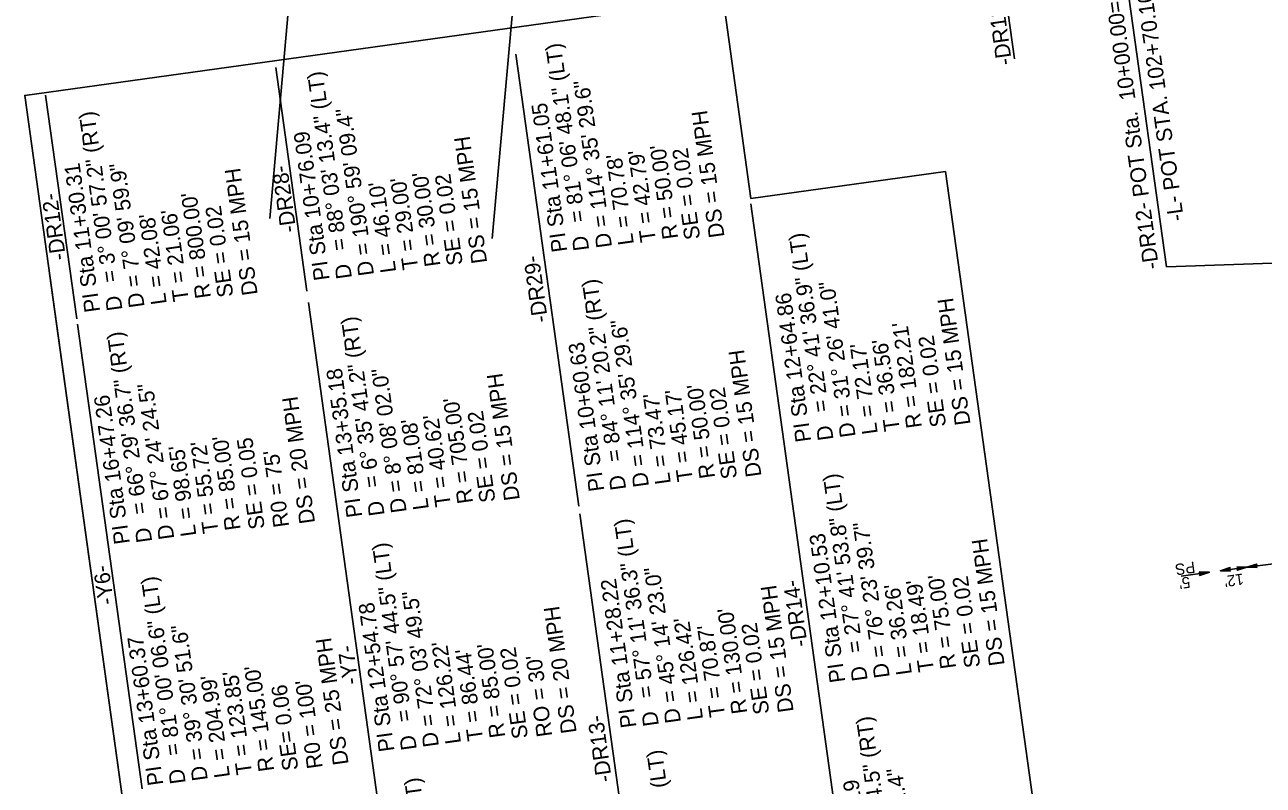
# Model space of a CAD drawing. Extents: x 472216 to 481979, y 489069 to 507339.
# Drawn here: x 477522 to 478077, y 496648 to 496989 of the extents above; entities that cross this region are included whole.
import ezdxf

# ---------------------------------------------------------------- set-up
doc = ezdxf.new("R2010")
doc.units = 0
for name, color, linetype in [('Exist Horizontal Alignment Point', 7, 'Continuous'), ('Old_Level_12', 7, 'Continuous'), ('Prop Rem of Exist Asph Pvmt', 7, 'Continuous'), ('Sheet Plot Border Outside CELL', 7, 'Continuous'), ('Sheet Sticker Incomplete CELL', 7, 'Continuous')]:
    doc.layers.add(name, color=color, linetype=linetype)

msp = doc.modelspace()

# ---------------------------------------------------------------- linework, layer by layer
at = {"layer": 'Exist Horizontal Alignment Point'}
msp.add_lwpolyline([(477581, 496533.88), (477522.1, 496957.12), (477834.84, 497000.65), (477847.32, 496910.94), (477934.43, 496923.06), (477980.85, 496589.53)], close=True, dxfattribs=at)
msp.add_lwpolyline([(477677.06, 496547.25), (477581, 496533.88), (477533.19, 496877.44)], dxfattribs=at)
at = {"layer": 'Old_Level_12'}
for p, q in [((477948.85, 497092.05), (477965.34, 496973.57)), ((478033.45, 496880.38), (478014.2, 497018.75)), ((478165.07, 496885.12), (478033.45, 496880.38))]:
    msp.add_line(p, q, dxfattribs=at)
at = {"layer": 'Prop Rem of Exist Asph Pvmt'}
for p, q in [((477770.17, 496773.32), (477742.01, 496975.64)), ((477648.47, 496869.48), (477634.53, 496969.68)), ((477545.37, 496857.08), (477531.42, 496957.28)), ((477892.86, 496581.03), (477847.28, 496908.56)), ((477692.61, 496552.35), (477649.18, 496864.39)), ((477574.64, 496646.77), (477545.7, 496854.7)), ((477798.8, 496567.57), (477770.65, 496769.88))]:
    msp.add_line(p, q, dxfattribs=at)
at = {"layer": 'Sheet Plot Border Outside CELL'}
for p, q in [((477675.74, 497395.08), (477631.85, 496902.03)), ((477775.34, 497386.21), (477731.46, 496893.16))]:
    msp.add_line(p, q, dxfattribs=at)
at = {"layer": 'Sheet Sticker Incomplete CELL'}
for p, q in [((478081.37, 496747.41), (478069.45, 496746.04)), ((478052.61, 496743.67), (478039.92, 496741.88)), ((478069.44, 496746.04), (478057.56, 496744.37))]:
    msp.add_line(p, q, dxfattribs=at)
for points in [[(478074, 496745.78), (478069.45, 496746.04), (478073.85, 496747.35), (478073.37, 496746.49)], [(478048.05, 496743.81), (478052.61, 496743.67), (478048.24, 496742.25), (478048.7, 496743.12)], [(478062.13, 496744.22), (478057.56, 496744.37), (478061.93, 496745.79), (478061.47, 496744.92)], [(478064.88, 496746.18), (478069.44, 496746.04), (478065.08, 496744.61), (478065.53, 496745.49)]]:
    msp.add_lwpolyline(points, close=True, dxfattribs=at)

# ---------------------------------------------------------------- texts
at = {"layer": 'Old_Level_12'}
for s, p in [('-DR13- PC Sta.  10+57.35', (477964.3, 496971.14)), ('-L- POT STA. 102+70.10', (478041.24, 496901.31)), ('-DR12- POT Sta.  10+00.00=', (478030.1, 496879.78))]:
    msp.add_text(s, height=7, rotation=97.9227, dxfattribs=at).set_placement(p)
at = {"layer": 'Prop Rem of Exist Asph Pvmt'}
for s, rotation, p in [('= 81%%d 06\' 48.1" (LT)', 97.9227, (477773.25, 496900.79)), ('= 88%%d 03\' 13.4" (LT)', 97.9227, (477666.59, 496888.16)), ('D = 114%%d 35\' 29.6"', 97.9227, (477785.12, 496889.38)), ('PI Sta 11+61.05', 97.9227, (477765.14, 496887.45)), ('= 3%%d 00\' 57.2" (RT)', 97.9227, (477563.82, 496873.9)), ('D = 190%%d 59\' 09.4"', 97.9227, (477678.55, 496876.85)), ('DS = 15 MPH', 97.9227, (477835.52, 496893.91)), ('PI Sta 10+76.09', 97.9227, (477658.65, 496874.76)), ('DS = 15 MPH', 97.9227, (477729.2, 496882.35)), ("L = 70.78'", 97.9227, (477794.9, 496890.65)), ("T = 42.79'", 97.9227, (477804.83, 496891.95)), ("R = 50.00'", 97.9227, (477814.76, 496893.24)), ('SE = 0.02', 97.9227, (477824.62, 496893.07)), ('PI Sta 11+30.31', 97.9227, (477555.89, 496860.51)), ('D = 7%%d 09\' 59.9"', 97.9227, (477575.79, 496862.6)), ('DS = 15 MPH', 97.9227, (477626.44, 496868.1)), ('-DR28-', 97.9227, (477643.75, 496896.21)), ("T = 29.00'", 97.9227, (477698.36, 496879.61)), ("R = 30.00'", 97.9227, (477708.27, 496880.99)), ('SE = 0.02', 97.9227, (477718.31, 496881.51)), ("L = 46.10'", 97.9227, (477688.46, 496878.23)), ('-DR12-', 97.9227, (477540.64, 496883.81)), ("R = 800.00'", 97.9227, (477605.51, 496866.73)), ('SE = 0.02', 97.9227, (477615.54, 496867.25)), ("L = 42.08'", 97.9227, (477585.7, 496863.97)), ("T = 21.06'", 97.9227, (477595.6, 496865.35)), ('D', 97.4336, (477774.87, 496888.01)), ('= 22%%d 41\' 36.9" (LT)', 97.9227, (477882.27, 496815.83)), ('D', 97.9227, (477668.65, 496875.47)), ('-DR29-', 97.9227, (477756.46, 496855.92)), ('= 84%%d 11\' 20.2" (RT)', 97.9227, (477789.82, 496793.66)), ('D = 31%%d 26\' 41.0"', 97.9227, (477894.23, 496804.52)), ('D', 97.9227, (477565.89, 496861.22)), ('PI Sta 12+64.86', 97.9227, (477874.33, 496802.43)), ('DS = 15 MPH', 97.9227, (477945.68, 496809.98)), ('= 6%%d 35\' 41.2" (RT)', 97.9227, (477681.21, 496782.05)), ('D = 114%%d 35\' 29.6"', 97.9227, (477801.67, 496782.25)), ("R = 182.21'", 97.9227, (477923.95, 496808.66)), ('= 66%%d 29\' 36.7" (RT)', 97.9227, (477577.12, 496770.11)), ("T = 36.56'", 97.9227, (477914.04, 496807.28)), ('SE = 0.02', 97.9227, (477934.78, 496809.13)), ('PI Sta 10+60.63', 97.9227, (477781.72, 496780.33)), ('DS = 15 MPH', 97.9227, (477852.07, 496786.79)), ("L = 72.17'", 97.9227, (477904.14, 496805.9)), ('PI Sta 13+35.18', 97.9227, (477673.28, 496768.66)), ('D = 8%%d 08\' 02.0"', 97.9227, (477693.18, 496770.74)), ('DS = 15 MPH', 97.9227, (477743.83, 496776.25)), ('D = 67%%d 24\' 24.5"', 97.9227, (477589.09, 496758.8)), ("T = 45.17'", 97.9227, (477821.37, 496784.82)), ("R = 50.00'", 97.9227, (477831.31, 496786.12)), ('SE = 0.02', 97.9227, (477841.17, 496785.94)), ('PI Sta 16+47.26', 97.9227, (477569.18, 496756.71)), ('DS = 20 MPH', 97.9227, (477652.13, 496765.87)), ("R = 705.00'", 97.9227, (477722.89, 496774.88)), ("L = 73.47'", 97.9227, (477811.46, 496783.53)), ("T = 40.62'", 97.9227, (477712.99, 496773.5)), ('SE = 0.02', 97.9227, (477732.93, 496775.4)), ("L = 81.08'", 97.9227, (477703.08, 496772.12)), ('D', 97.9227, (477884.33, 496803.15)), ("R = 85.00'", 97.9227, (477618.8, 496762.94)), ('SE = 0.05', 97.9227, (477629.63, 496763.41)), ("L = 98.65'", 97.9227, (477598.99, 496760.18)), ("T = 55.72'", 97.9227, (477608.9, 496761.56)), ("R0 = 75'", 97.9227, (477640.53, 496764.26)), ('D', 97.9227, (477791.45, 496780.92)), ('= 27%%d 41\' 53.8" (LT)', 97.9227, (477897.56, 496708.11)), ('D', 97.9227, (477683.27, 496769.37)), ('= 57%%d 11\' 36.3" (LT)', 97.9227, (477804.02, 496687.9)), ('D = 76%%d 23\' 39.7"', 97.9227, (477909.52, 496696.8)), ('D', 97.9227, (477579.18, 496757.43)), ('PI Sta 12+10.53', 97.9227, (477889.62, 496694.72)), ('DS = 15 MPH', 97.9227, (477960.97, 496702.26)), ('= 90%%d 57\' 44.5" (LT)', 97.9227, (477695.64, 496677.2)), ('-Y6-', 97.9227, (477562.01, 496729.62)), ('= 81%%d 00\' 06.6" (LT)', 97.9227, (477592.15, 496662.09)), ('D = 45%%d 14\' 23.0"', 97.9227, (477815.99, 496676.59)), ("R = 75.00'", 97.9227, (477939.24, 496700.94)), ('SE = 0.02', 97.9227, (477950.07, 496701.41)), ('PI Sta 11+28.22', 97.9227, (477796.09, 496674.5)), ('DS = 15 MPH', 97.9227, (477866.47, 496681.4)), ('-DR14-', 97.9227, (477872.73, 496710.74)), ("L = 36.26'", 97.9227, (477919.43, 496698.18)), ("T = 18.49'", 97.9227, (477929.33, 496699.56)), ('D = 72%%d 03\' 49.5"', 97.9227, (477707.61, 496665.9)), ('PI Sta 12+54.78', 97.9227, (477687.7, 496663.81)), ('DS = 20 MPH', 97.9227, (477769.3, 496671.99)), ("R = 130.00'", 97.9227, (477845.71, 496680.73)), ('D = 39%%d 30\' 51.6"', 97.9227, (477604.12, 496650.78)), ("L = 126.42'", 97.9227, (477825.9, 496677.97)), ("T = 70.87'", 97.9227, (477835.8, 496679.35)), ('SE = 0.02', 97.9227, (477855.57, 496680.55)), ('PI Sta 13+60.37', 97.9227, (477584.22, 496648.69)), ('DS = 25 MPH', 97.9227, (477667.16, 496657.85)), ('-Y7-', 97.9227, (477671.55, 496693.85)), ("L = 126.22'", 97.9227, (477717.51, 496667.27)), ("T = 86.44'", 97.9227, (477727.42, 496668.65)), ("R = 85.00'", 97.9227, (477737.32, 496670.03)), ('SE = 0.02', 97.9227, (477747.51, 496669.63)), ("RO = 30' ", 97.9227, (477758.41, 496670.47)), ("T = 123.85'", 97.9227, (477623.93, 496653.54)), ("R = 145.00'", 97.9227, (477633.83, 496654.92)), ('D', 97.9227, (477899.62, 496695.43)), ("L = 204.99'", 97.9227, (477614.02, 496652.16)), ('SE= 0.06', 97.9227, (477644.66, 496655.39)), ("R0 = 100'", 97.9227, (477655.56, 496656.24)), ('D', 97.9227, (477806.09, 496675.21)), ('-DR13-', 97.9227, (477785.09, 496650.17)), ('= 33%%d 33\' 54.5" (RT)', 97.9227, (477912.59, 496597.91)), ('D', 97.9227, (477697.7, 496664.52)), ('= 49%%d 09\' 14.4" (LT)', 97.9227, (477818.54, 496584.44)), ('D', 97.9227, (477594.21, 496649.4)), ('D = 28%%d 38\' 52.4"', 97.9227, (477924.56, 496586.6)), ('= 62%%d 23\' 11.4" (RT)', 97.9227, (477710.23, 496570.47)), ('PI Sta 11+35.19', 97.9227, (477904.66, 496584.51))]:
    msp.add_text(s, height=7, rotation=rotation, dxfattribs=at).set_placement(p)
at = {"layer": 'Sheet Sticker Incomplete CELL'}
for s, p in [('PS', (478045.88, 496748.5)), ("5'", (478043.65, 496741.79)), ("12'", (478067.64, 496743.19))]:
    msp.add_text(s, height=5, rotation=188.0081, dxfattribs=at).set_placement(p)

doc.saveas('drawing.dxf')
